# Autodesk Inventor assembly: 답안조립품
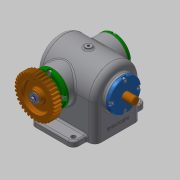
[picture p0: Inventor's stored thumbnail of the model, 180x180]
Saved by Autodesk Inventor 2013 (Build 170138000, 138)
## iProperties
Created: 2019-05
Part Number: 답안조립품
Document SubType Name: Assembly
Designer: Administrator
Author: Administrator
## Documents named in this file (16)
- C:\Users\Administrator\Desktop\390504V1043\답안조립품.iam
- C:\Users\Administrator\Desktop\390504V1043\가변스프링.ipt
- C:\Users\Administrator\Desktop\390504V1043\가이드부시.ipt
- C:\Users\Administrator\Desktop\390504V1043\베어링 6203.ipt
- C:\Users\Administrator\Desktop\390504V1043\본체.ipt
- C:\Users\Administrator\Desktop\390504V1043\볼트 M4x8.ipt
- C:\Users\Administrator\Desktop\390504V1043\볼트 M4x10.ipt
- C:\Users\Administrator\Desktop\390504V1043\스퍼기어.ipt
- C:\Users\Administrator\Desktop\390504V1043\스프링와셔.ipt
- C:\Users\Administrator\Desktop\390504V1043\슬라이더.ipt
- C:\Users\Administrator\Desktop\390504V1043\오일 실 17 32 8.ipt
- C:\Users\Administrator\Desktop\390504V1043\커버 A.ipt
- C:\Users\Administrator\Desktop\390504V1043\커버 B.ipt
- C:\Users\Administrator\Desktop\390504V1043\키 4x4x14.ipt
- C:\Users\Administrator\Desktop\390504V1043\편심축.ipt
- C:\Users\Administrator\Desktop\390504V1043\평와셔.ipt
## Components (2 placed, 2 different names)
1. 가변스프링:1
2. 가이드부시:1
